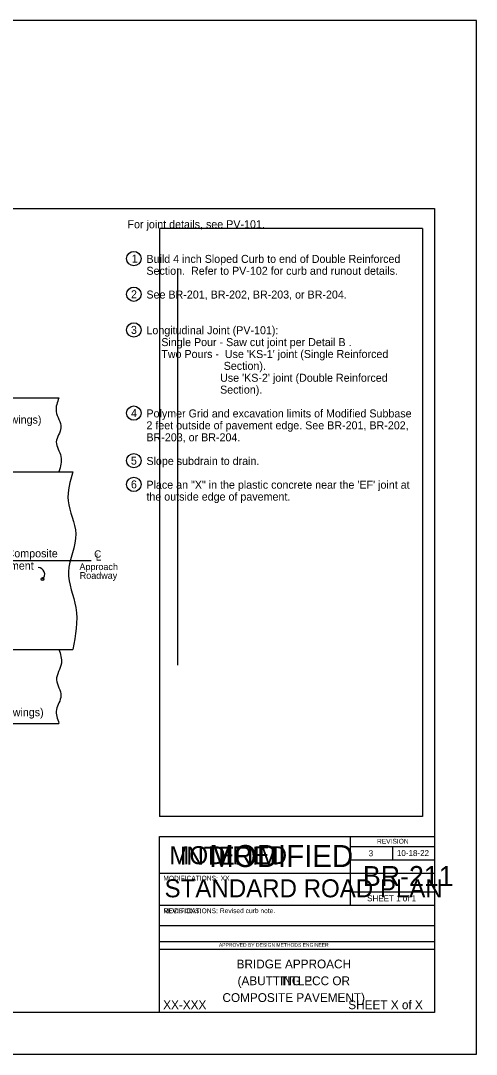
# Model space of a CAD drawing. Extents: x -2135039 to -2131695, y -2139150 to -2136566.
# Drawn here: x -2132834 to -2131695, y -2139150 to -2136566 of the extents above; entities that cross this region are included whole.
import ezdxf

# ---------------------------------------------------------------- set-up
doc = ezdxf.new("R2010")
doc.units = 0
for name, color, linetype in [('dsnDOTLogo', 7, 'Continuous'), ('dsnNonPlotable', 7, 'Continuous'), ('dsnStdBlock', 7, 'Continuous'), ('dsnstdblockInterim', 7, 'Continuous'), ('dsnStdLogo', 7, 'Continuous'), ('dsnstdModifiedBlock', 7, 'Continuous'), ('Level 1', 7, 'Continuous'), ('Level 2', 7, 'Continuous'), ('Level 3', 7, 'Continuous')]:
    doc.layers.add(name, color=color, linetype=linetype)

msp = doc.modelspace()

# ---------------------------------------------------------------- linework, layer by layer
at = {"layer": 'dsnDOTLogo'}
msp.add_lwpolyline([(-2135038.9, -2139150.4), (-2131694.9, -2139150.4), (-2131694.9, -2136566.4), (-2135038.9, -2136566.4)], close=True, dxfattribs=at)
at = {"layer": 'dsnNonPlotable'}
for p, q in [((-2132487.5, -2137085.9), (-2132487.5, -2138555.9)), ((-2131829.4, -2137085.9), (-2132487.5, -2137085.9)), ((-2131829.4, -2137085.9), (-2131829.4, -2138555.9)), ((-2132442.5, -2137185.9), (-2132442.5, -2138177.5)), ((-2131829.4, -2138555.9), (-2132487.5, -2138555.9))]:
    msp.add_line(p, q, dxfattribs=at)
at = {"layer": 'dsnStdLogo'}
for p, q in [((-2132010.4, -2138605.9), (-2132010.4, -2138697.3)), ((-2132010.4, -2138630.9), (-2131799.4, -2138630.9)), ((-2131904.9, -2138630.9), (-2131904.9, -2138664.1)), ((-2132010.4, -2138664.1), (-2131799.4, -2138664.1)), ((-2132487.5, -2138697.3), (-2132010.4, -2138697.3)), ((-2132010.4, -2138697.3), (-2132010.4, -2138777.3)), ((-2131799.4, -2138745.1), (-2132010.4, -2138745.1)), ((-2132487.5, -2138777.3), (-2131799.4, -2138777.3)), ((-2132487.5, -2138828.3), (-2131799.4, -2138828.3)), ((-2132487.5, -2138868.3), (-2131799.4, -2138868.3)), ((-2132487.5, -2138887.3), (-2131799.4, -2138887.3))]:
    msp.add_line(p, q, dxfattribs=at)
msp.add_lwpolyline([(-2132487.5, -2138605.9), (-2131799.4, -2138605.9), (-2131799.4, -2139045.9), (-2132487.5, -2139045.9)], close=True, dxfattribs=at)
at = {"layer": 'dsnstdModifiedBlock'}
for p, q in [((-2132487.5, -2138697.3), (-2131799.4, -2138697.3)), ((-2132487.5, -2138887.3), (-2131799.4, -2138887.3))]:
    msp.add_line(p, q, dxfattribs=at)
msp.add_lwpolyline([(-2132487.5, -2138605.9), (-2131799.4, -2138605.9), (-2131799.4, -2139045.9), (-2132487.5, -2139045.9)], close=True, dxfattribs=at)
at = {"layer": 'Level 1'}
msp.add_lwpolyline([(-2134934.4, -2137035.9), (-2131799.4, -2137035.9), (-2131799.4, -2139045.9), (-2134934.4, -2139045.9)], close=True, dxfattribs=at)
at = {"layer": 'Level 2'}
for p, q in [((-2133249.3, -2137509), (-2132738.5, -2137509)), ((-2133249.3, -2137694), (-2132703.7, -2137694)), ((-2134174.5, -2137916), (-2132658.2, -2137916)), ((-2133249.3, -2138138.1), (-2132703.7, -2138138.1)), ((-2133249.3, -2138323.1), (-2132738.5, -2138323.1))]:
    msp.add_line(p, q, dxfattribs=at)
for centre, radius in [((-2132551.3, -2137161.2), 18), ((-2132551.3, -2137250.3), 18), ((-2132551.3, -2137339.5), 18), ((-2132551.3, -2137547.5), 18), ((-2132551.3, -2137666.3), 18), ((-2132551.3, -2137725.7), 18), ((-2132779.6, -2137962.4), 3.6)]:
    msp.add_circle(centre, radius, dxfattribs=at)
for points in [[(-2132738.5, -2137509), (-2132745.4, -2137543.2), (-2132733.7, -2137583.9), (-2132745.1, -2137619.4), (-2132733.7, -2137656), (-2132738.5, -2137694)], [(-2132703.7, -2137694), (-2132715.6, -2137766.7), (-2132696.3, -2137849.3), (-2132714.8, -2137944.2), (-2132696.3, -2138033.7), (-2132703.7, -2138138.1)], [(-2132738.5, -2138138.1), (-2132732.5, -2138172.8), (-2132744.5, -2138214.6), (-2132733.5, -2138254.4), (-2132744.8, -2138288.8), (-2132738.5, -2138323.1)]]:
    msp.add_spline(points, degree=3, dxfattribs=at)
at = {"layer": 'Level 3'}
msp.add_arc((-2132790.5, -2137950), 16.4, 311.309, 90, dxfattribs=at)

# ---------------------------------------------------------------- texts
at = {"layer": 'dsnNonPlotable'}
msp.add_text('REVISIONS:', height=12, dxfattribs=at).set_placement((-2132477.5, -2138797.6))
at = {"layer": 'dsnStdBlock'}
for s, height, p in [('MODIFIED', 45, (-2132462.4, -2138675.1)), ('MODIFICATIONS:', 12, (-2132477.5, -2138797.6))]:
    msp.add_text(s, height=height, dxfattribs=at).set_placement(p)
at = {"layer": 'dsnstdblockInterim'}
msp.add_text('INTERIM', height=45, dxfattribs=at).set_placement((-2132436.5, -2138676.3))
at = {"layer": 'dsnStdLogo'}
for s, height, p in [('REVISION', 12, (-2131943.4, -2138623.8)), ('3', 15, (-2131964.1, -2138655.3)), ('10-18-22', 15, (-2131893.5, -2138654.8)), ('BR-211', 50, (-2131978.5, -2138729.8)), ('STANDARD ROAD PLAN', 45.001, (-2132474.4, -2138757.9)), ('SHEET 1 of 1', 15, (-2131968, -2138767.9)), ('Revised curb note.', 12, (-2132336.1, -2138797.5)), ('APPROVED BY DESIGN METHODS ENGINEER', 9.003, (-2132338.5, -2138881.4)), ('BRIDGE APPROACH', 22, (-2132294.3, -2138935.6)), ('(ABUTTING PCC OR', 22, (-2132291.9, -2138977.6)), ('COMPOSITE PAVEMENT)', 22, (-2132329.7, -2139019.6))]:
    msp.add_text(s, height=height, dxfattribs=at).set_placement(p)
at = {"layer": 'dsnstdModifiedBlock'}
for s, height, p in [('MODIFIED', 55, (-2132362.4, -2138682.2)), ('MODIFICATIONS:', 12, (-2132477.5, -2138716.1)), ('XX', 12, (-2132334.2, -2138716.1)), ('TITLE', 22, (-2132185.4, -2138977.6)), ('XX-XXX', 22, (-2132477.9, -2139037.6)), ('SHEET X of X', 22, (-2132015.1, -2139037.6))]:
    msp.add_text(s, height=height, dxfattribs=at).set_placement(p)
at = {"layer": 'Level 3'}
for s, height, p in [('For joint details, see PV-101.', 20, (-2132567.1, -2137085.4)), ('1', 20, (-2132556.5, -2137171.2)), ('Build 4 inch Sloped Curb to end of Double Reinforced', 20, (-2132519.8, -2137172)), ('Section.  Refer to PV-102 for curb and runout details.', 20, (-2132519.8, -2137201.7)), ('2', 20, (-2132558.4, -2137260.3)), ('See BR-201, BR-202, BR-203, or BR-204.', 20, (-2132519.8, -2137261.1)), ('3', 20, (-2132558.5, -2137349.5)), ('Longitudinal Joint (PV-101):', 20, (-2132519.8, -2137350.3)), ('     Single Pour - Saw cut joint per Detail B .', 20, (-2132519.8, -2137380)), ("     Two Pours -  Use 'KS-1' joint (Single Reinforced", 20, (-2132519.8, -2137409.7)), ('                          Section).', 20, (-2132519.8, -2137439.4)), ("     Use 'KS-2' joint (Double Reinforced", 20, (-2132372.8, -2137469.1)), ('     Section).', 20, (-2132372.8, -2137498.8)), ('(See Project Typical Drawings)', 20, (-2133149.3, -2137573.8)), ('4', 20, (-2132558.4, -2137557.5)), ('Polymer Grid and excavation limits of Modified Subbase', 20, (-2132519.8, -2137558.3)), ('2 feet outside of pavement edge. See BR-201, BR-202, ', 20, (-2132519.8, -2137588)), ('BR-203, or BR-204.', 20, (-2132519.8, -2137618)), ('5', 20, (-2132558.6, -2137676.3)), ('Slope subdrain to drain.', 20, (-2132519.8, -2137677.1)), ('6', 20, (-2132558.5, -2137735.7)), ('Place an "X" in the plastic concrete near the \'EF\' joint at', 20, (-2132519.8, -2137736.5)), ('the outside edge of pavement.', 20, (-2132519.8, -2137766.2)), ('P.C.C. or Composite', 20, (-2132986.8, -2137908.1)), ('C', 18.4, (-2132650.5, -2137908.9)), ('Pavement', 20, (-2132922.1, -2137938.8)), ('L', 18.4, (-2132646.6, -2137916.1)), ('Approach', 16.8, (-2132687.3, -2137939.9)), ('Roadway', 16.8, (-2132686.5, -2137961.8)), ('(See Project Typical Drawings)', 20, (-2133143.9, -2138305.2))]:
    msp.add_text(s, height=height, dxfattribs=at).set_placement(p)

doc.saveas('drawing.dxf')
